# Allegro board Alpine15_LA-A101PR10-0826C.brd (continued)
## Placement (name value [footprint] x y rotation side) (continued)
Q11  PMST3904_SOT323-3~D  [PMST3904_SOT323-3]  142.6 74.84 90 top
Q12  MMST3904-7-F_SOT323-3~D  [MMST3904-7-F_SOT323-3]  171.58 135.2 270 top
Q13  PMST3904_SOT323-3~D  [PMST3904_SOT323-3]  62.03 67.6 270 top
Q14  PMST3904_SOT323-3~D  [PMST3904_SOT323-3]  172.9 113.86 180 top
Q15  PMST3904_SOT323-3~D  [PMST3904_SOT323-3]  156.9 53 90 bottom
Q16  PDTA114EU_SC70-3~D  [PDTA114EU_SC70-3]  226.79 32.33 270 top
Q19  DMN66D0LDW-7_SOT363-6~D  [DMN66D0LDW-7_SOT363-6]  223.08 105.15 90 bottom
Q20  -  [L2N7002WT1G_SC-70-3]  317.46 155.36 270 bottom
Q21  DMN66D0LDW-7_SOT363-6~D  [DMN66D0LDW-7_SOT363-6]  320.68 156.18 0 bottom
Q22  DMN66D0LDW-7_SOT363-6~D  [DMN66D0LDW-7_SOT363-6]  248.73 165.28 90 bottom
Q24  DMN66D0LDW-7_SOT363-6~D  [DMN66D0LDW-7_SOT363-6]  222.41 37.82 180 top
Q26  PDTA114EU_SC70-3~D  [PDTA114EU_SC70-3]  224.6 37.57 90 top
Q28  DMN66D0LDW-7_SOT363-6~D  [DMN66D0LDW-7_SOT363-6]  209.07 143.56 180 top
Q30  DMN66D0LDW-7_SOT363-6~D  [DMN66D0LDW-7_SOT363-6]  250.63 164.11 270 bottom
Q32  DMN66D0LDW-7_SOT363-6~D  [DMN66D0LDW-7_SOT363-6]  203.71 163.68 0 top
Q122  DMN66D0LDW-7_SOT363-6~D  [DMN66D0LDW-7_SOT363-6]  16.66 106.58 0 top
Q123  DMN66D0LDW-7_SOT363-6~D  [DMN66D0LDW-7_SOT363-6]  300.22 149.37 270 bottom
Q124  SI3457CDV-T1-GE3_TSOP6~D  [SI3457CDV-T1-GE3_TSOP6]  96.6 155.58 180 bottom
Q125  DMN66D0LDW-7_SOT363-6~D  [DMN66D0LDW-7_SOT363-6]  85.43 148.24 0 bottom
Q126  -  [LP2301ALT1G_SOT23-3]  86.86 158.7 0 bottom
Q133  BSS138W-7-F_SOT323-3~D  [BSS138W-7-F_SOT323-3]  161.43 166.09 180 top
Q135  BSS138W-7-F_SOT323-3~D  [BSS138W-7-F_SOT323-3]  167.59 166.53 270 top
Q137  -  [LP2301ALT1G_SOT23-3]  89.65 163.23 90 bottom
Q138  -  [LP2301ALT1G_SOT23-3]  84.85 137.36 90 bottom
Q140  DMN66D0LDW-7_SOT363-6~D  [DMN66D0LDW-7_SOT363-6]  95.92 162.54 180 bottom
Q142  -  [SI3456DDV-T1-GE3_TSOP6]  162.76 106.41 180 top
Q143  DMN66D0LDW-7_SOT363-6~D  [DMN66D0LDW-7_SOT363-6]  161.63 109.4 270 top
QC1  DMN66D0LDW-7_SOT363-6~D  [DMN66D0LDW-7_SOT363-6]  187.23 75.92 180 top
QC4  DMN66D0LDW-7_SOT363-6~D  [DMN66D0LDW-7_SOT363-6]  219.34 54.35 90 top
QC6  DMN66D0LDW-7_SOT363-6~D  [DMN66D0LDW-7_SOT363-6]  75.68 100.61 180 bottom
QC8  DMN66D0LDW-7_SOT363-6~D  [DMN66D0LDW-7_SOT363-6]  73.23 116.87 90 bottom
QC9  DMN66D0LDW-7_SOT363-6~D  [DMN66D0LDW-7_SOT363-6]  67.22 121.72 180 bottom
QC11  DMN66D0LDW-7_SOT363-6~D  [DMN66D0LDW-7_SOT363-6]  68.76 97.62 270 top
QD1  -  [BSS138-G_SOT23-3]  228.51 32.04 270 top
QV2806  DMN66D0LDW-7_SOT363-6~D  [DMN66D0LDW-7_SOT363-6]  26.95 119.65 0 bottom
QZ5  -  [DMN66D0LDW-7_SOT363-6]  29.05 118.16 270 top
QZ21  -  [DMN66D0LDW-7_SOT363-6]  59.2 87.28 270 top
QZ22  -  [DMN66D0LDW-7_SOT363-6]  17.8 111.29 270 bottom
R1  1K_0402_5%~D  [R_0402]  177.31 75.55 270 bottom
R2  1K_0402_5%~D  [R_0402]  172.5 70.02 180 bottom
R3  0_0402_5%~D  [R_0402]  203.22 64.6 90 bottom
R4  33_0402_5%~D  [R_0402]  204.11 64.6 90 bottom
R5  33_0402_5%~D  [R_0402]  208.55 65.52 270 bottom
R6  33_0402_5%~D  [R_0402]  204.99 64.6 90 bottom
R7  33_0402_5%~D  [R_0402]  207.66 65.52 270 bottom
R8  0_0402_5%~D  [R_0402]  191.66 132.19 270 top
R9  33_0402_5%~D  [R_0402]  205.88 65.52 270 bottom
R10  0_0402_5%~D  [R_0402]  203.72 73.62 90 bottom
R11  33_0402_5%~D  [R_0402]  207.28 73.62 90 bottom
R12  33_0402_5%~D  [R_0402]  206.39 73.62 90 bottom
R13  33_0402_5%~D  [R_0402]  205.5 73.62 90 bottom
R14  0_0402_5%~D  [R_0402]  199.2 71.67 0 bottom
R15  33_0402_5%~D  [R_0402]  199.66 62.95 90 bottom
R16  33_0402_5%~D  [R_0402]  198.39 63.87 270 bottom
R17  0_0402_5%~D  [R_0402]  202.84 73.62 90 bottom
R18  33_0402_5%~D  [R_0402]  204.61 73.62 90 bottom
R19  33_0402_5%~D  [R_0402]  201.44 62.95 90 bottom
R20  33_0402_5%~D  [R_0402]  196.61 63.87 270 bottom
R21  33_0402_5%~D  [R_0402]  195.6 63.87 270 bottom
R22  33_0402_5%~D  [R_0402]  201.95 73.62 90 bottom
R23  0_0402_5%~D  [R_0402]  200.55 63.87 270 bottom
R24  1K_0402_5%~D  [R_0402]  122.62 84.62 0 bottom
R25  100K_0402_5%~D  [R_0402]  193.69 153.74 180 top
R26  100K_0402_5%~D  [R_0402]  248.73 151.8 0 bottom
R27  100K_0402_5%~D  [R_0402]  13.97 31.21 90 bottom
R28  220K_0402_5%~D  [R_0402]  232.35 31.99 270 top
R29  66.5_0402_1%  [R_0402]  124.73 14.06 90 bottom
R30  66.5_0402_1%  [R_0402]  125.62 14.06 90 bottom
R31  66.5_0402_1%  [R_0402]  199.42 14.21 90 top
R32  2M_0402_5%~D  [R_0402]  233.24 31.99 270 top
R33  66.5_0402_1%  [R_0402]  200.57 14.21 90 top
R34  0_0402_5%~D  [R_0402]  230.64 25.92 180 top
R35  10K_0402_5%~D  [R_0402]  175.61 125.77 180 top
R36  100K_0402_5%~D  [R_0402]  200.34 132.16 270 top
R37  0_0402_5%~D  [R_0402]  185.29 93.79 270 top
R39  20K_0402_1%~D  [R_0402]  314.18 151.01 0 bottom
R40  2.7K_0402_5%~D  [R_0402]  171.67 158.91 180 top
R41  33_0402_5%~D  [R_0402]  201.06 73.62 90 bottom
R42  2.7K_0402_5%~D  [R_0402]  171.64 159.84 180 top
R43  33_0402_5%~D  [R_0402]  205.62 83.69 90 bottom
R44  1M_0402_5%~D  [R_0402]  182.48 169.54 90 top
R45  33_0402_5%~D  [R_0402]  197.5 62.95 90 bottom
R46  2.2K_0402_5%~D  [R_0402]  171.64 162.63 180 top
R47  1M_0402_5%~D  [R_0402]  183.37 169.54 90 top
R48  33_0402_5%~D  [R_0402]  204.67 83.69 90 bottom
R49  2.2K_0402_5%~D  [R_0402]  171.64 163.58 180 top
R50  0_0402_5%~D  [R_0402]  185.06 85.84 270 bottom
R51  0_0402_5%~D  [R_0402]  185.94 85.84 270 bottom
R52  0_0402_5%  [R0402_0OHM]  223.04 117.42 90 bottom
R53  1M_0402_1%  [R_0402]  32.4 54.44 90 bottom
R54  2.7K_0402_5%~D  [R_0402]  187.39 162.34 0 top
R55  2.2K_0402_5%~D  [R_0402]  173.75 151.5 270 top
R56  0_0402_5%~D  [R_0402]  186.83 85.84 270 bottom
R57  33_0402_5%~D  [R_0402]  206.77 64.6 90 bottom
R58  33_0402_5%~D  [R_0402]  203.65 83.69 90 bottom
R59  33_0402_5%~D  [R_0402]  202.76 83.69 90 bottom
R60  0_0402_5%~D  [R_0402]  187.72 85.84 270 bottom
R61  0_0402_5%~D  [R_0402]  224.65 135.01 180 top
R62  0_0402_5%~D  [R_0402]  224.65 134.12 180 top
R64  10K_0402_5%~D  [R_0402]  168.04 149.19 90 top
R65  2.2K_0402_5%~D  [R_0402]  159.4 151.09 90 top
R66  1M_0402_5%~D  [R_0402]  187.24 153.09 90 top
R67  0_0402_5%~D  [R_0402]  225.57 133.26 180 top
R68  0_0402_5%~D  [R_0402]  225.57 132.37 180 top
R69  1M_0402_5%~D  [R_0402]  174.64 151.5 270 top
R71  0_0402_5%~D  [R_0402]  80.92 36.74 0 bottom
R73  0_0402_5%~D  [R_0402]  213.25 122.03 180 top
R74  2.7K_0402_5%~D  [R_0402]  190.21 158.15 180 top
R75  0_0402_5%~D  [R_0402]  213.25 121.11 180 top
R76  0_0402_5%~D  [R_0402]  212.15 122.9 180 top
R77  0_0402_5%  [R0402_0OHM]  213.01 122.91 90 top
R91  1M_0402_5%~D  [R_0402]  171.67 160.82 180 top
R92  1M_0402_5%~D  [R_0402]  171.67 161.71 180 top
R93  0_0402_5%~D  [R_0402]  80.92 37.63 0 bottom
R94  0_0402_5%~D  [R_0402]  80.92 34.84 0 bottom
R95  0_0402_5%~D  [R_0402]  80.92 35.72 0 bottom
R96  0_0402_5%~D  [R_0402]  80.92 35.85 0 top
R97  0_0402_5%~D  [R_0402]  80.92 34.96 0 top
R98  0_0402_5%~D  [R_0402]  80.92 36.74 0 top
R99  0_0402_5%~D  [R_0402]  80.92 37.63 0 top
R100  0_0402_5%~D  [R_0402]  71.39 78.98 270 bottom
R101  0_0402_5%~D  [R_0402]  70.5 78.98 270 bottom
R102  0_0402_5%~D  [R_0402]  154.19 91.15 90 top
R104  0_0402_5%~D  [R_0402]  155.08 91.15 90 top
R105  0_0402_5%~D  [R_0402]  71.39 78.98 270 top
R106  0_0402_5%~D  [R_0402]  70.5 78.98 270 top
R107  0_0402_5%  [R0402_0OHM]  188.18 152.18 180 top
R108  100K_0402_5%~D  [R_0402]  164.48 108.29 90 top
R109  10K_0402_5%~D  [R_0402]  159.26 109.02 270 top
R110  0_0402_5%  [R0402_0OHM]  89.68 143.12 270 bottom
R120  1M_0402_5%~D  [R_0402]  166.88 184.76 270 top
R121  1M_0402_5%~D  [R_0402]  165.62 173.34 270 bottom
R122  10K_0402_5%~D  [R_0402]  217.77 127.52 270 top
R123  10K_0402_5%~D  [R_0402]  219.09 127.49 270 top
R124  10K_0402_5%~D  [R_0402]  224.13 118.34 270 bottom
R125  100K_0402_5%~D  [R_0402]  223.92 107.58 180 bottom
R126  100K_0402_5%~D  [R_0402]  224.14 104.02 0 bottom
R130  0_0805_5%  [R0805_0OHM]  277.51 171.91 180 bottom
R136  33_0402_5%~D  [R_0402]  309.24 159.6 270 bottom
R137  BLM15AG700SN1D_0402  [R_0402]  191.64 173.57 270 bottom
R139  BLM15AG700SN1D_0402  [R_0402]  188.09 173.57 270 bottom
R141  33_0402_5%~D  [R_0402]  190.75 173.57 270 bottom
R142  0_0402_5%~D  [R_0402]  300.34 147.01 0 bottom
R143  0_0402_5%  [R0402_0OHM]  188.98 173.57 270 bottom
R144  0_0402_5%  [R0402_0OHM]  189.87 173.57 270 bottom
R148  47_0402_5%~D  [R_0402]  307.34 158.68 90 bottom
R149  33_0402_5%~D  [R_0402]  308.23 158.68 90 bottom
R150  10K_0402_5%~D  [R_0402]  301.28 155.33 0 bottom
R152  39.2K_0402_1%~D  [R_0402]  313.71 158.58 90 bottom
R153  0_0402_5%  [R0402_0OHM]  299.35 156.73 180 bottom
R154  0_0402_5%  [R0402_0OHM]  269.86 184.03 0 bottom
R155  0_0402_5%  [R0402_0OHM]  87.95 80.94 0 bottom
R156  39.2K_0402_1%~D  [R_0402]  314.6 158.58 90 bottom
R157  20K_0402_1%~D  [R_0402]  315.48 158.58 90 bottom
R158  100K_0402_5%~D  [R_0402]  320.69 158.36 270 bottom
R159  100K_0402_5%~D  [R_0402]  319.68 158.36 270 bottom
R160  10K_0402_5%~D  [R_0402]  310.48 161.33 180 bottom
R161  100K_0402_5%~D  [R_0402]  159.4 166.86 270 top
R162  18_0402_5%  [R_0402]  314.47 149.64 0 top
R163  100K_0402_5%~D  [R_0402]  316.93 161.33 0 bottom
R164  100K_0402_5%~D  [R_0402]  168.93 166.48 270 top
R165  0_0402_5%  [R0402_0OHM]  90.77 80.94 180 bottom
R166  18_0402_5%  [R_0402]  314.47 148.75 0 top
R167  10K_0402_5%~D  [R_0402]  311.34 162.22 0 bottom
R168  10K_0402_5%~D  [R_0402]  107.13 115.35 0 top
R169  0_0402_5%  [R0402_0OHM]  192.64 145.42 0 top
R170  10K_0402_5%~D  [R_0402]  107.13 114.46 0 top
R171  10K_0402_5%~D  [R_0402]  197.42 155.53 270 top
R172  10K_0402_5%~D  [R_0402]  196.47 155.53 270 top
R175  0_0402_5%  [R0402_0OHM]  197.86 142.93 90 top
R176  4.7K_0402_5%~D  [R_0402]  194.7 143.52 180 top
R178  4.7K_0402_5%~D  [R_0402]  193.79 144.41 0 top
R179  0_0402_5%  [R0402_0OHM]  193.79 142.63 0 top
R180  0_0402_5%  [R0402_0OHM]  196.92 142.06 180 top
R181  0_0603_5%~D  [R0603_0OHM]  205.87 143.71 90 top
R183  0_0402_5%  [R0402_0OHM]  200.66 142.04 90 top
R184  1K_0402_5%~D  [R_0402]  199.77 154.62 90 top
R185  3.01K_0402_1%~D  [R_0402]  204.28 144.74 270 top
R187  2.2K_0402_5%  [R_0402]  310.2 147.09 270 bottom
R193  0_0402_5%  [R0402_0OHM]  188.1 135.67 90 top
R197  2.2K_0402_5%  [R_0402]  309.31 147.09 270 bottom
R201  0_0402_5%~D  [R_0402]  192.17 154.89 90 top
R205  191_0402_1%~D  [R_0402]  25.17 20.67 90 bottom
R206  1M_0402_5%~D  [R_0402]  200.65 143.84 0 top
R208  100K_0402_5%~D  [R_0402]  298.39 151.4 270 bottom
R211  4.7K_0402_1%~D  [R_0402]  20.45 31.85 90 bottom
R212  100K_0402_5%~D  [R_0402]  17.52 25.24 90 bottom
R214  100K_0402_5%~D  [R_0402]  16.64 26.16 270 bottom
R215  0_0402_5%~D  [R_0402]  311.42 177.36 0 bottom
R216  2.2K_0402_5%~D  [R_0402]  245.82 154.88 180 bottom
R217  2.2K_0402_5%~D  [R_0402]  245.82 157.55 180 bottom
R218  0_0402_5%~D  [R_0402]  244.91 155.77 0 bottom
R219  0_0402_5%~D  [R_0402]  244.91 156.66 0 bottom
R223  0_0402_5%  [R0402_0OHM]  326.91 176.24 90 bottom
R224  0_0402_5%~D  [R_0402]  320.39 181.77 180 top
R225  0_0402_5%~D  [R_0402]  327.8 176.24 90 bottom
R226  100K_0402_5%~D  [R_0402]  247.71 162.68 90 bottom
R227  100K_0402_5%~D  [R_0402]  247.71 165.09 90 bottom
R228  0_0402_5%~D  [R_0402]  313.88 177.38 270 bottom
R229  100K_0402_5%~D  [R_0402]  251.78 164.23 270 bottom
R230  10_0402_5%~D  [R_0402]  27.61 25.95 0 bottom
R231  0_0402_5%  [R0402_0OHM]  31.41 33.05 90 bottom
R232  2.7K_0402_5%~D  [R_0402]  171.67 158.03 180 top
R233  0_0402_5%  [R0402_0OHM]  314.77 177.38 270 bottom
R234  0_0402_5%  [R0402_0OHM]  308.17 177.12 270 bottom
R236  0_0402_5%  [R0402_0OHM]  307.28 177.12 270 bottom
R238  0_0402_5%  [R0402_0OHM]  304.61 177.12 270 bottom
R239  0_0402_5%  [R0402_0OHM]  305.5 177.12 270 bottom
R240  0_0402_5%  [R0402_0OHM]  306.39 177.12 270 bottom
R241  0_0402_5%  [R0402_0OHM]  309.82 186.85 0 top
R244  0_0402_5%  [R0402_0OHM]  314.21 187.36 180 top
R246  0_0402_5%~D  [R_0402]  21.11 77.19 180 bottom
R247  0_0402_5%~D  [R_0402]  21.11 78.21 180 bottom
R248  0_0402_5%~D  [R_0402]  20.76 79.12 180 bottom
R249  0_0402_5%~D  [R_0402]  21.95 80.29 180 top
R250  0_0402_5%~D  [R_0402]  20.76 80.26 180 bottom
R251  0_0402_5%~D  [R_0402]  21.95 81.31 180 top
R252  0_0402_5%  [R0402_0OHM]  167.64 172.46 90 bottom
R253  0_0402_5%  [R0402_0OHM]  168.65 172.46 90 bottom
R254  0_0402_5%  [R0402_0OHM]  170.15 173.38 270 top
R255  0_0402_5%  [R0402_0OHM]  169.61 172.46 90 bottom
R256  0_0402_5%  [R0402_0OHM]  171.11 173.38 270 top
R257  0_0402_5%  [R0402_0OHM]  170.62 172.46 90 bottom
R258  0_0402_5%  [R0402_0OHM]  174.05 173.38 270 top
R259  0_0402_5%  [R0402_0OHM]  166.72 172.46 90 bottom
R260  0_0402_5%  [R0402_0OHM]  168.22 173.38 270 top
R261  0_0402_5%  [R0402_0OHM]  169.14 173.38 270 top
R262  0_0402_5%  [R0402_0OHM]  172.12 173.38 270 top
R263  0_0402_5%  [R0402_0OHM]  171.54 172.46 90 bottom
R264  0_0402_5%  [R0402_0OHM]  173.04 173.38 270 top
R265  0_0402_5%  [R0402_0OHM]  172.55 172.46 90 bottom
R266  0_0402_5%  [R0402_0OHM]  173.47 172.46 90 bottom
R267  0_0402_5%  [R0402_0OHM]  174.94 173.38 270 top
R268  100K_0402_5%~D  [R_0402]  175.02 173.44 90 bottom
R269  0_0402_5%  [R0402_0OHM]  183.91 180.29 90 top
R270  0_0402_5%  [R0402_0OHM]  184.8 180.29 90 top
R271  100K_0402_5%~D  [R_0402]  176.67 184.16 0 top
R272  10K_0402_5%~D  [R_0402]  201.32 184.62 180 top
R273  33_0402_5%~D  [R_0402]  198.87 177.13 0 top
R274  0_0402_5%  [R0402_0OHM]  186.77 180.2 90 top
R275  0_0402_5%  [R0402_0OHM]  189 180.22 90 top
R276  0_0402_5%  [R0402_0OHM]  187.68 180.19 90 top
R277  0_0402_5%  [R0402_0OHM]  189.87 180.22 90 top
R282  100K_0402_5%~D  [R_0402]  182.69 118.78 0 top
R283  100K_0402_5%~D  [R_0402]  199.99 120.05 180 top
R284  100K_0402_5%~D  [R_0402]  194.82 132.16 270 top
R285  100K_0402_5%~D  [R_0402]  187.21 115.15 90 top
R286  100K_0402_5%~D  [R_0402]  199.99 121.83 180 top
R288  10K_0402_5%~D  [R_0402]  188.1 115.15 90 top
R289  100K_0402_5%~D  [R_0402]  196.72 132.16 270 top
R290  33_0402_5%~D  [R_0402]  181.04 134.32 270 top
R291  10K_0402_5%~D  [R_0402]  191.02 115.15 90 top
R292  100K_0402_5%~D  [R_0402]  199.99 120.94 180 top
R293  100K_0402_5%~D  [R_0402]  185.94 132.12 270 top
R294  0_0402_5%  [R0402_0OHM]  199.84 128.82 0 top
R295  100K_0402_5%~D  [R_0402]  190.14 115.15 90 top
R296  10K_0402_5%~D  [R_0402]  201.62 119.24 270 top
R297  0_0402_5%  [R0402_0OHM]  30.26 33.05 90 bottom
R298  100K_0402_5%~D  [R_0402]  190.62 132.18 270 top
R302  100K_0402_5%~D  [R_0402]  202.49 120.22 180 top
R303  100K_0402_5%~D  [R_0402]  192.72 132.29 270 top
R304  10K_0402_5%~D  [R_0402]  202.76 124.88 0 top
R305  100K_0402_5%~D  [R_0402]  185.06 132.12 270 top
R306  0_0402_5%  [R0402_0OHM]  29.25 33.05 90 bottom
R307  100K_0402_5%~D  [R_0402]  182.67 119.72 0 top
R308  100K_0402_5%~D  [R_0402]  200.75 127.93 180 top
R309  100K_0402_5%~D  [R_0402]  189.25 115.15 90 top
R310  10K_0402_5%~D  [R_0402]  194.96 115.15 90 top
R311  150_0402_1%~D  [R_0402]  186.07 158.66 0 top
R312  150_0402_1%~D  [R_0402]  186.07 160.06 0 top
R313  100K_0402_5%~D  [R_0402]  194.07 115.15 90 top
R315  0_0402_5%  [R0402_0OHM]  27.98 33.05 90 bottom
R316  0_0402_5%  [R0402_0OHM]  197.76 115.15 90 top
R317  100K_0402_5%~D  [R_0402]  199.84 126.15 0 top
R318  0_0402_5%  [R0402_0OHM]  189.74 132.18 270 top
R319  0_0402_5%  [R0402_0OHM]  182.68 130.37 0 top
R320  100K_0402_5%~D  [R_0402]  200.75 127.04 180 top
R321  1K_0402_5%~D  [R_0402]  183.59 129.42 180 top
R322  100K_0402_5%~D  [R_0402]  202.49 121.11 180 top
R323  0_0402_5%~D  [R_0402]  199.83 125.21 0 top
R324  33_0402_5%~D  [R_0402]  183.59 122.51 180 top
R325  10_0402_1%~D  [R_0402]  202.49 122 180 top
R326  1K_0402_5%~D  [R_0402]  193.61 131.38 90 top
R327  100K_0402_5%~D  [R_0402]  160.4 112.72 0 top
R328  100K_0402_5%~D  [R_0402]  158.44 116.22 270 top
R329  10K_0402_5%~D  [R_0402]  161.31 111.83 180 top
R330  10K_0402_5%~D  [R_0402]  160.21 116.22 270 top
R331  10K_0402_5%~D  [R_0402]  195.51 157.31 270 top
R332  0_0402_5%  [R0402_0OHM]  154.37 121.74 0 top
R333  0_0402_5%  [R0402_0OHM]  25.75 33.05 90 bottom
R334  0_0402_5%  [R0402_0OHM]  161.81 134.33 90 top
R335  10K_0402_5%~D  [R_0402]  160.04 135.24 270 top
R336  0_0402_5%  [R0402_0OHM]  175.61 123.99 180 top
R337  0_0402_5%  [R0402_0OHM]  27.02 33.05 90 bottom
R338  1K_0402_5%~D  [R_0402]  165.24 115.3 270 top
R339  0_0402_5%~D  [R_0402]  78.35 117.85 270 bottom
R340  10K_0402_5%~D  [R_0402]  170.07 132.7 270 top
R341  0_0402_5%  [R0402_0OHM]  27.61 23.86 0 bottom
R342  100K_0402_5%~D  [R_0402]  160.93 135.24 270 top
R343  100K_0402_5%~D  [R_0402]  165.12 132.7 270 top
R344  0_0402_5%~D  [R_0402]  76.57 118.35 0 bottom
R345  0_0402_5%~D  [R_0402]  76.57 117.44 0 bottom
R346  0_0402_5%~D  [R_0402]  77.65 99.1 90 bottom
R347  0_0402_5%~D  [R_0402]  76.75 100.01 270 bottom
R348  0_0402_5%~D  [R_0402]  79.24 117.85 270 bottom
R349  1K_0402_5%~D  [R_0402]  157.7 129.58 180 top
R350  0_0402_5%~D  [R_0402]  80.13 117.8 90 bottom
R351  150_0402_1%~D  [R_0402]  186.07 161.45 0 top
R352  1K_0402_5%~D  [R_0402]  164.92 112.54 270 top
R353  100K_0402_5%~D  [R_0402]  310.48 162.22 180 bottom
R354  10K_0402_5%~D  [R_0402]  200.75 123.99 180 top
R355  0_0402_5%~D  [R_0402]  78.35 118.72 0 bottom
R358  100K_0402_5%~D  [R_0402]  164.03 112.54 270 top
R360  100K_0402_5%~D  [R_0402]  140.39 137.57 90 top
R362  100K_0402_5%~D  [R_0402]  164.35 114.39 90 top
R363  100K_0402_5%~D  [R_0402]  169.18 132.7 270 top
R366  10K_0402_5%~D  [R_0402]  167.15 132.7 270 top
R367  1K_0402_5%~D  [R_0402]  157.83 119.29 180 top
R370  100K_0402_5%~D  [R_0402]  157.83 120.18 180 top
R371  100K_0402_5%~D  [R_0402]  175.61 126.78 180 top
R373  8.2K_0402_5%~D  [R_0402]  168.04 132.7 270 top
R374  0_0402_5%  [R0402_0OHM]  158.14 131.39 180 top
R375  43_0402_5%~D  [R_0402]  155.21 133.49 90 top
R376  10K_0402_5%~D  [R_0402]  175.48 117.51 180 top
R378  0_0402_5%  [R0402_0OHM]  157.3 114.93 90 top
R379  0_0402_5%  [R0402_0OHM]  156.78 125.77 0 top
R380  100K_0402_5%~D  [R_0402]  155.72 123.94 270 top
R381  4.7K_0402_5%~D  [R_0402]  157.7 124.88 180 top
R382  10_0402_1%~D  [R_0402]  174.69 128.69 0 top
R383  1K_0402_5%~D  [R_0402]  174.69 130.59 0 top
R384  100_0402_1%~D  [R_0402]  156.61 123.02 90 top
R386  1K_0402_5%~D  [R_0402]  167.59 110.99 90 top
R387  100K_0402_5%~D  [R_0402]  311.34 163.11 0 bottom
R388  49.9_0402_1%~D  [R_0402]  220.67 90.72 0 top
R389  100K_0402_5%~D  [R_0402]  72.03 95.16 180 top
R391  100K_0402_5%~D  [R_0402]  189.12 135.6 90 top
R392  33K_0402_5%  [R_0402]  166.26 114.39 90 top
R393  10K_0402_5%~D  [R_0402]  163.09 110.94 180 top
R394  1.58K_0402_1%  [R_0402]  174.56 116.62 0 top
R395  10K_0402_5%~D  [R_0402]  220.67 91.73 0 top
R396  10K_0402_5%~D  [R_0402]  221.76 100.04 90 top
R397  10K_0402_5%~D  [R_0402]  224.43 100.04 90 top
R398  100K_0402_5%~D  [R_0402]  220.67 92.62 0 top
R399  10K_0402_5%~D  [R_0402]  163.09 111.83 180 top
R400  0_0402_5%  [R0402_0OHM]  222.65 100.04 90 top
R402  8.2K_0402_5%~D  [R_0402]  173.5 132.7 270 top
R403  2.2K_0402_5%~D  [R_0402]  170.34 135.29 270 top
R404  4.7K_0402_5%~D  [R_0402]  149.42 103.96 270 top
R405  4.7K_0402_5%~D  [R_0402]  149.42 105.33 90 top
R406  0_0402_5%  [R0402_0OHM]  223.54 100.04 90 top
R407  0_0402_5%  [R0402_0OHM]  186.11 183.64 90 top
R408  10K_0402_5%~D  [R_0402]  175.61 124.88 180 top
R410  0_0402_5%  [R0402_0OHM]  27.61 24.75 0 bottom
R411  33_0402_5%~D  [R_0402]  168.67 141.06 90 top
R413  0_0402_5%  [R0402_0OHM]  163.45 138.61 90 top
R414  0_0402_5%~D  [R_0402]  164.4 138.61 90 top
R415  0_0402_5%  [R0402_0OHM]  185.22 183.64 90 top
R416  0_0402_5%  [R0402_0OHM]  167.59 108.71 270 top
R417  0_0402_5%~D  [R_0402]  165.82 108.71 270 top
R418  0_0402_5%  [R0402_0OHM]  166.7 108.71 270 top
R419  100K_0402_5%~D  [R_0402]  187.77 132.16 270 top
R421  0_0402_5%~D  [R_0402]  196.59 111.04 180 top
R422  0_0402_5%  [R0402_0OHM]  196.59 110.15 180 top
R423  0_0402_5%~D  [R_0402]  196.69 109.26 180 top
R424  0_0402_5%  [R0402_0OHM]  196.69 108.37 180 top
R425  0_0402_5%~D  [R_0402]  253.25 160.82 0 bottom
R426  0_0402_5%  [R0402_0OHM]  253.25 161.71 0 bottom
R428  10K_0402_5%~D  [R_0402]  223.54 38.31 90 top
R429  300_0402_5%  [R_0402]  226.28 35.85 180 top
R432  100K_0402_5%~D  [R_0402]  208.88 140.7 180 top
R433  300_0402_5%~D  [R_0402]  226.28 34.96 180 top
R435  300_0402_5%~D  [R_0402]  226.28 34.07 180 top
R436  300_0402_5%~D  [R_0402]  210.2 143.7 270 top
R438  300_0402_5%~D  [R_0402]  227.65 37.88 0 top
R440  10K_0402_5%~D  [R_0402]  167.83 139.25 90 top
R441  0_0402_5%  [R0402_0OHM]  148.53 103.96 270 top
R443  0_0402_5%  [R0402_0OHM]  18.29 33.4 270 bottom
R444  0_0402_5%  [R0402_0OHM]  148.53 105.33 90 top
R449  0_0402_5%~D  [R_0402]  147.58 105.33 90 top
R450  0_0402_5%~D  [R_0402]  147.58 103.96 270 top
R459  100K_0402_5%~D  [R_0402]  172.49 79.46 180 top
R460  10K_0402_5%~D  [R_0402]  14.88 109.51 90 bottom
R461  0_0402_5%  [R0402_0OHM]  153.09 117.67 0 top
R462  680_0402_1%  [R_0402]  18.18 106.72 270 bottom
R463  680_0402_1%  [R_0402]  18.18 107.61 90 bottom
R464  680_0402_1%  [R_0402]  17.16 103.42 270 bottom
R465  680_0402_1%  [R_0402]  17.16 98.08 270 bottom
R466  680_0402_1%  [R_0402]  17.16 104.3 90 bottom
R467  680_0402_1%  [R_0402]  18.05 100.75 270 bottom
R468  680_0402_1%  [R_0402]  17.16 99.1 90 bottom
R469  680_0402_1%  [R_0402]  18.05 101.64 90 bottom
R470  2.2K_0402_5%~D  [R_0402]  19.32 106.59 0 top
R471  2.2K_0402_5%~D  [R_0402]  15.59 108.5 180 top
R472  0_0402_5%~D  [R_0402]  15.59 109.38 180 top
R473  10K_0402_5%~D  [R_0402]  11.57 113.19 270 top
R474  20K_0402_5%~D  [R_0402]  14.88 111.42 90 bottom
R475  1M_0402_5%~D  [R_0402]  19.16 112.2 270 bottom
R476  10K_0402_5%~D  [R_0402]  341.39 159.85 90 top
R477  10K_0402_5%~D  [R_0402]  101.62 178.32 270 top
R478  10K_0402_5%~D  [R_0402]  225.93 39.23 180 top
R479  10K_0402_5%~D  [R_0402]  312.44 166.53 270 top
R480  10K_0402_5%~D  [R_0402]  245.3 161.96 0 bottom
R481  10K_0402_5%~D  [R_0402]  186.88 131.25 90 top
R482  0_0402_5%  [R0402_0OHM]  246.28 158.48 180 bottom
R483  0_0402_5%  [R0402_0OHM]  246.28 159.62 180 bottom
R484  100K_0402_5%~D  [R_0402]  188.74 132.19 270 top
R485  0_0402_5%~D  [R_0402]  109.34 116.57 0 top
R486  0_0402_5%  [R0402_0OHM]  93.76 13.95 90 top
R487  0_0402_5%  [R0402_0OHM]  94.75 13.95 90 top
R488  0_0402_5%~D  [R_0402]  109.4 112.91 0 top
R490  10K_0402_5%~D  [R_0402]  109.41 126.53 0 top
R491  2.2K_0402_5%~D  [R_0402]  156.46 135.27 270 top
R492  2.2K_0402_5%~D  [R_0402]  157.35 135.27 270 top
R556  4.7K_0402_5%~D  [R_0402]  188.31 167.3 180 top
R734  0_0402_5%  [R0402_0OHM]  76.67 27.09 180 bottom
R741  0_0402_5%  [R0402_0OHM]  195.49 87.46 0 top
R742  0_0402_5%  [R0402_0OHM]  195.49 88.47 0 top
R2576  100K_0402_5%~D  [R_0402]  92.6 157.85 270 bottom
R2577  100K_0402_5%~D  [R_0402]  168.93 94.22 270 top
R2578  47K_0402_5%~D  [R_0402]  91.71 156.93 90 bottom
R2579  0_0402_5%  [R0402_0OHM]  103.34 154.47 180 bottom
R2580  0_0402_5%  [R0402_0OHM]  103.34 155.49 180 bottom
R2581  100K_0402_5%~D  [R_0402]  138.75 110.68 90 top
R2582  2.2K_0402_5%~D  [R_0402]  112.53 122.56 180 top
R2583  12K_0402_1%  [R_0402]  125.19 119.54 180 top
R2584  2.2K_0402_5%~D  [R_0402]  112.53 123.45 180 top
R2585  10K_0402_5%~D  [R_0402]  128.67 122.85 180 top
R2586  100K_0402_5%~D  [R_0402]  112.51 120.95 180 top
R2588  0_0402_5%  [R0402_0OHM]  99.08 159.47 90 bottom
R2590  4.7K_0402_5%~D  [R_0402]  107.84 122.01 90 top
R2591  4.7K_0402_5%~D  [R_0402]  110.51 122.01 90 top
R2592  4.7K_0402_5%~D  [R_0402]  107.84 120.1 90 top
R2593  4.7K_0402_5%~D  [R_0402]  110.51 120.1 90 top
R2594  0_0402_5%  [R0402_0OHM]  100.09 159.47 90 bottom
R2595  0_0402_5%  [R0402_0OHM]  106.32 159.63 270 top
R2596  0_0402_5%  [R0402_0OHM]  106.32 156.3 90 top
R2597  0_0402_5%  [R0402_0OHM]  126.56 121.45 0 top
R2598  0_0402_5%  [R0402_0OHM]  126.56 120.56 0 top
R2599  0_0402_5%  [R0402_0OHM]  101.57 143.65 0 top
R2600  0_0402_5%  [R0402_0OHM]  101.59 142.79 0 top
R2601  0_0402_5%~D  [R_0402]  87.93 154.95 270 bottom
R2602  0_0402_5%  [R0402_0OHM]  87.04 154.95 270 bottom
R2605  47K_0402_5%~D  [R_0402]  93.49 165.09 270 bottom
R2626  2K_0402_5%  [R_0402]  300.75 161.28 270 top
R2627  4.7K_0402_5%~D  [R_0402]  294.15 162.85 0 top
R2628  4.7K_0402_5%~D  [R_0402]  298.09 160.36 90 top
R2629  4.7K_0402_5%~D  [R_0402]  299.86 160.36 90 top
R2630  4.7K_0402_5%~D  [R_0402]  298.97 160.36 90 top
R2631  4.7K_0402_5%~D  [R_0402]  301.77 160.36 90 top
R2633  4.7K_0402_5%~D  [R_0402]  300.16 170.19 270 top
R2634  4.7K_0402_5%~D  [R_0402]  297.37 170.19 270 top
R2635  4.7K_0402_5%~D  [R_0402]  299.21 170.19 270 top
R2636  4.7K_0402_5%~D  [R_0402]  298.26 170.19 270 top
R2637  4.7K_0402_5%~D  [R_0402]  296.48 170.19 270 top
R2644  4.99K_0402_1%~D  [R_0402]  302.78 161.28 270 top
R2646  0_0402_5%~D  [R_0402]  295.1 164.69 180 bottom
R2647  0_0402_5%~D  [R_0402]  295.1 163.74 180 bottom
R2648  0_0402_5%~D  [R_0402]  303.72 167.04 0 bottom
R2649  0_0402_5%~D  [R_0402]  303.72 166.15 0 bottom
R2650  0_0402_5%~D  [R_0402]  304.64 164.88 180 bottom
R2651  0_0402_5%~D  [R_0402]  304.64 163.99 180 bottom
R2652  0_0402_5%~D  [R_0402]  294.18 165.64 0 bottom
R2653  0_0402_5%~D  [R_0402]  294.18 166.59 0 bottom
R2654  0_0402_5%  [R0402_0OHM]  304.64 164.88 180 top
R2655  0_0402_5%  [R0402_0OHM]  304.64 163.99 180 top
R2656  0_0402_5%  [R0402_0OHM]  303.72 167.04 0 top
R2657  0_0402_5%  [R0402_0OHM]  303.72 166.15 0 top
R2658  0_0402_5%~D  [R_0402]  186.83 85.84 270 top
R2659  0_0402_5%~D  [R_0402]  187.72 85.84 270 top
R2660  0_0402_5%~D  [R_0402]  185.06 85.84 270 top
R2661  0_0402_5%~D  [R_0402]  185.94 85.84 270 top
R2662  0_0402_5%~D  [R_0402]  225.54 132.35 180 bottom
R2663  0_0402_5%~D  [R_0402]  225.54 133.23 180 bottom
R2664  0_0402_5%~D  [R_0402]  224.65 134.12 180 bottom
R2665  0_0402_5%~D  [R_0402]  224.65 135.01 180 bottom
R2678  100K_0402_5%~D  [R_0402]  97.37 140.37 180 bottom
R2688  0_0603_5%~D  [R0603_0OHM]  288.5 146.47 180 top
R2689  12K_0402_1%~D  [R_0402]  227.32 46.87 0 top
R2691  10K_0402_5%~D  [R_0402]  216.63 50.96 180 top
R2692  10K_0402_5%~D  [R_0402]  216.63 51.98 180 top
R2693  10K_0402_5%~D  [R_0402]  216.42 55.54 270 top
R2694  0_0402_5%  [R0402_0OHM]  217.79 45.27 0 top
R2695  100K_0402_5%~D  [R_0402]  218.13 50.96 0 top
R2696  100K_0402_5%~D  [R_0402]  218.08 53.07 270 top
R2697  0_0402_5%  [R0402_0OHM]  217.79 46.41 0 top
R2698  100K_0402_5%~D  [R_0402]  217.57 57.7 270 top
R2699  0_0402_5%  [R0402_0OHM]  216.63 49.06 180 top
R2700  10K_0402_5%~D  [R_0402]  218.99 49.06 180 top
R2701  10K_0402_5%~D  [R_0402]  218.99 48.17 180 top
R2702  0_0603_5%~D  [R0603_0OHM]  288.37 148.65 180 top
R2703  0_0603_5%~D  [R0603_0OHM]  288.37 150.91 180 top
R2704  0_0603_5%~D  [R0603_0OHM]  288.37 153.35 180 top
R2705  3.74K_0402_1%  [R_0402]  186.07 157.52 0 top
R3000  100_0402_1%~D  [R_0402]  147.01 109.51 0 top
RC1  330K_0402_1%~D  [R_0402]  165.71 55.66 0 top
RC2  330K_0402_1%~D  [R_0402]  186.33 54.22 270 top
RC3  1K_0402_1%~D  [R_0402]  171.09 53.94 90 top
RC4  0_0402_5%  [R0402_0OHM]  179.21 58.25 90 top
RC5  10M_0402_5%~D  [R_0402]  179.21 56.48 90 top
RC6  20K_0402_5%~D  [R_0402]  202.78 60.53 270 bottom
RC7  1M_0402_5%~D  [R_0402]  165.62 58.38 90 top
RC8  20K_0402_5%~D  [R_0402]  197.25 59.68 270 bottom
RC9  1K_0402_1%~D  [R_0402]  172.86 53.94 90 top
RC10  1K_0402_1%~D  [R_0402]  99.85 82.75 90 bottom
RC11  100K_0402_5%~D  [R_0402]  176.09 72.17 0 bottom
RC12  10K_0402_5%~D  [R_0402]  176.09 70.14 0 bottom
RC14  0_0402_5%  [R0402_0OHM]  165.6 93.28 180 top
RC16  0_0603_5%  [R0603_0OHM]  102.67 72.3 90 bottom
RC17  51_0402_1%~D  [R_0402]  102.77 83.66 270 bottom
RC18  51_0402_1%~D  [R_0402]  100.74 82.75 90 bottom
RC19  3.01K_0402_1%~D  [R_0402]  164.68 92.39 0 top
RC20  51_0402_1%~D  [R_0402]  101.53 72.73 90 bottom
RC22  51_0402_1%~D  [R_0402]  96.9 82.77 90 bottom
RC23  33_0402_5%~D  [R_0402]  171.97 53.94 90 top
RC24  33_0402_5%~D  [R_0402]  160.15 54.69 90 top
RC25  33_0402_5%~D  [R_0402]  163.47 58.38 90 top
RC26  33_0402_5%~D  [R_0402]  162.58 58.38 90 top
RC27  10K_0402_5%~D  [R_0402]  173.03 68.22 180 bottom
RC28  2.2K_0402_5%~D  [R_0402]  184.93 73.49 90 top
RC30  2.2K_0402_5%~D  [R_0402]  184.93 76.19 270 top
RC32  0_0402_5%~D  [R_0402]  115.33 118.99 270 top
RC33  0_0402_5%  [R0402_0OHM]  168.04 94.22 270 top
RC36  2.2K_0402_5%~D  [R_0402]  180.86 71.97 90 bottom
RC37  2.2K_0402_5%~D  [R_0402]  179.98 71.97 90 bottom
RC38  0_0402_5%  [R0402_0OHM]  203.88 58.44 180 top
RC40  0_0402_5%  [R0402_0OHM]  149.45 91.43 180 top
RC44  1M_0402_5%~D  [R_0402]  151.23 91.43 180 top
RC45  3.01K_0402_1%~D  [R_0402]  156.61 91.22 90 top
RC46  10K_0402_5%~D  [R_0402]  146.57 91.48 90 top
RC47  10K_0402_5%~D  [R_0402]  145.69 91.48 90 top
RC48  0_0402_5%  [R0402_0OHM]  142.53 94.72 90 top
RC49  0_0402_5%  [R0402_0OHM]  141.64 94.72 90 top
RC50  10K_0402_5%~D  [R_0402]  170.07 59.3 270 top
RC52  10K_0402_5%~D  [R_0402]  179.34 54.85 270 top
RC53  0_0402_5%  [R0402_0OHM]  141.62 92.32 270 top
RC54  0_0402_5%  [R0402_0OHM]  142.51 92.32 270 top
RC55  10K_0402_5%~D  [R_0402]  178.25 77.76 0 bottom
RC58  22_0402_5%~D  [R_0402]  213.03 54.14 0 top
RC59  0_0402_5%  [R0402_0OHM]  143.84 91.47 90 top
RC60  0_0402_5%  [R0402_0OHM]  144.8 91.47 90 top
RC61  22_0402_5%~D  [R_0402]  213.03 56.77 90 top
RC63  22_0402_5%~D  [R_0402]  203.86 57.57 270 top
RC64  22_0402_5%~D  [R_0402]  169.05 57.01 270 top
RC65  0_0402_5%  [R0402_0OHM]  170.45 57.01 270 top
RC66  22_0402_5%~D  [R_0402]  168.16 57.01 270 top
RC67  1.8K_0402_1%  [R_0402]  99.58 13.04 90 top
RC68  2_0402_1%  [R_0402]  101.4 13.96 270 top
RC69  1.8K_0402_1%  [R_0402]  100.47 13.96 270 top
RC70  10K_0402_5%~D  [R_0402]  186.38 60.74 0 top
RC72  0_0402_5%  [R0402_0OHM]  185.94 78.6 270 bottom
RC73  330K_0402_1%~D  [R_0402]  188.18 57.97 90 top
RC74  10K_0402_5%~D  [R_0402]  183.61 75.35 180 top
RC76  8.2K_0402_5%~D  [R_0402]  183.53 81.11 90 bottom
RC78  330K_0402_1%~D  [R_0402]  187.26 58.89 270 top
RC79  0_0402_5%~D  [R_0402]  164.35 59.3 270 top
RC80  8.2K_0402_5%~D  [R_0402]  178.25 78.65 0 bottom
RC81  8.2K_0402_5%~D  [R_0402]  184.42 82.03 270 bottom
RC82  0_0402_5%~D  [R_0402]  185.13 61.81 180 top
RC83  24.9_0402_1%~D  [R_0402]  103.9 13.96 270 top
RC84  0_0402_5%~D  [R_0402]  181.88 53.55 90 top
RC85  100_0402_1%~D  [R_0402]  177.45 96.73 90 top
RC86  0_0402_5%  [R0402_0OHM]  178.71 75.55 270 bottom
RC87  0_0402_5%  [R0402_0OHM]  186.33 58 90 top
RC88  0_0402_5%  [R0402_0OHM]  180.86 53.55 90 top
RC90  0_0402_5%  [R0402_0OHM]  189.63 73.52 270 top
RC91  0_0402_5%  [R0402_0OHM]  190.52 73.52 270 top
RC92  0_0402_5%  [R0402_0OHM]  188.74 73.52 270 top
RC93  0_0402_5%  [R0402_0OHM]  164.52 56.6 90 top
RC94  0_0402_5%  [R0402_0OHM]  187.29 61.76 180 top
RC95  0_0402_5%~D  [R_0402]  100.74 81.5 270 bottom
RC96  0_0402_5%~D  [R_0402]  101.88 83.66 270 bottom
RC97  0_0402_5%~D  [R_0402]  98.96 83.66 270 bottom
RC98  10K_0402_5%~D  [R_0402]  179.59 74.64 90 bottom
RC99  1K_0402_1%~D  [R_0402]  101.16 57.7 0 top
RC100  0_0402_5%  [R0402_0OHM]  203.01 54.9 0 top
RC101  0_0402_5%~D  [R_0402]  100.58 72.73 90 bottom
RC102  1K_0402_1%~D  [R_0402]  101.16 49.41 0 top
RC103  0_0402_5%~D  [R_0402]  102.52 81.5 270 bottom
RC104  0_0402_5%~D  [R_0402]  101.63 80.59 90 bottom
RC105  1K_0402_1%~D  [R_0402]  102.07 43.7 180 top
RC106  1K_0402_1%~D  [R_0402]  102.07 44.61 180 top
RC107  0_0402_5%  [R0402_0OHM]  102.06 45.7 180 top
RC108  0_0402_5%  [R0402_0OHM]  102.06 47.53 180 top
RC109  1K_0402_1%~D  [R_0402]  102.07 55.92 180 top
RC110  0_0402_5%  [R0402_0OHM]  102.07 50.3 180 top
RC111  0_0402_5%  [R0402_0OHM]  102.07 51.32 180 top
RC112  0_0402_5%  [R0402_0OHM]  102.07 52.21 180 top
RC113  49.9_0402_1%~D  [R_0402]  118.88 77.14 0 bottom
RC114  62_0402_5%~D  [R_0402]  115.56 76.14 180 top
RC115  10K_0402_5%~D  [R_0402]  119.21 73.98 270 top
RC116  1K_0402_1%~D  [R_0402]  186.58 82.21 90 top
RC117  56_0402_5%~D  [R_0402]  121.23 78.09 0 bottom
RC118  51_0402_1%~D  [R_0402]  121.23 82.28 0 bottom
RC119  51_0402_1%~D  [R_0402]  119.73 83.23 180 bottom
RC120  51_0402_1%~D  [R_0402]  121.23 77.07 0 bottom
RC121  0_0402_5%~D  [R_0402]  119.73 79.1 180 bottom
RC122  51_0402_1%~D  [R_0402]  118.81 81.2 0 bottom
RC123  0_0402_5%~D  [R_0402]  99.87 80.59 90 bottom
RC124  0_0402_5%~D  [R_0402]  97.79 83.69 270 bottom
RC125  200_0402_1%~D  [R_0402]  133.56 69.51 180 top
RC126  2_0402_1%  [R_0402]  157.4 25.84 180 top
RC127  51_0402_1%~D  [R_0402]  98.95 80.56 90 bottom
RC128  24.9_0402_1%~D  [R_0402]  155.6 24 0 top
RC129  121_0402_1%  [R_0402]  124.73 62.06 90 bottom
RC130  1.8K_0402_1%  [R_0402]  158.4 25 90 top
RC131  51_0402_1%~D  [R_0402]  98.67 72.73 90 bottom
RC132  1.8K_0402_1%  [R_0402]  157.46 24.95 180 top
RC133  100_0402_1%~D  [R_0402]  130.89 69.16 90 top
RC134  24.9_0402_1%~D  [R_0402]  154.32 81.19 0 top
RC135  0_0402_5%~D  [R_0402]  99.56 73.64 270 bottom
RC136  10K_0402_5%~D  [R_0402]  164.01 54.61 90 top
RC137  100K_0402_5%~D  [R_0402]  178.83 94.22 270 top
RC138  10K_0402_5%~D  [R_0402]  174.32 74.43 270 bottom
RC139  0_0402_5%~D  [R_0402]  175.23 93.38 180 top
RC140  10K_0402_5%~D  [R_0402]  175.66 97.65 270 top
RC141  0_0402_5%~D  [R_0402]  122.88 60.11 0 bottom
RC142  0_0402_5%  [R0402_0OHM]  102.07 53.1 180 top
RC143  0_0402_5%~D  [R_0402]  124.78 85.64 0 bottom
RC144  0_0402_5%~D  [R_0402]  189.18 59.68 0 top
RC145  0_0402_5%~D  [R_0402]  178.88 59.85 0 bottom
RC146  10K_0402_5%~D  [R_0402]  183.61 82.97 180 top
RC147  100K_0402_5%~D  [R_0402]  169.43 97.65 270 top
RC148  10K_0402_5%~D  [R_0402]  174.97 76.57 180 bottom
RC149  100K_0402_5%~D  [R_0402]  177.05 94.22 270 top
RC152  100K_0402_5%~D  [R_0402]  169.82 94.22 270 top
RC153  100K_0402_5%~D  [R_0402]  168.55 97.27 270 top
RC154  1K_0402_1%~D  [R_0402]  171.99 75.07 270 top
RC155  100K_0402_5%~D  [R_0402]  171.59 94.22 270 top
RC156  100K_0402_5%~D  [R_0402]  170.7 94.22 270 top
RC157  0_0402_5%~D  [R_0402]  58.94 79.74 270 top
RC158  100K_0402_5%~D  [R_0402]  172.48 93.31 90 top
RC159  22.6_0402_1%~D  [R_0402]  160.37 59.22 180 top
RC160  0_0402_5%~D  [R_0402]  92.81 14.38 90 bottom
RC161  3.01K_0402_1%~D  [R_0402]  152.67 97.32 270 top
RC162  0_0402_5%~D  [R_0402]  110.32 111.12 180 top
RC163  0_0402_5%  [R0402_0OHM]  147.59 92.37 270 top
RC164  0_0402_5%~D  [R_0402]  92.81 14.38 90 top
RC165  0_0402_5%~D  [R_0402]  58.94 79.74 270 bottom
RC166  10K_0402_5%~D  [R_0402]  179.72 94.22 270 top
RC168  49.9_0402_1%~D  [R_0402]  160.37 58.33 180 top
RC169  10K_0402_5%~D  [R_0402]  175.1 71.16 180 bottom
RC170  100K_0402_5%~D  [R_0402]  176.09 71.16 0 bottom
RC172  0_0402_5%  [R0402_0OHM]  124.78 84.62 0 bottom
RC173  2_0402_1%  [R_0402]  80.08 25.56 0 bottom
RC174  0_0402_5%  [R0402_0OHM]  183.61 83.98 180 top
RC175  10K_0402_5%~D  [R_0402]  180.79 62.01 0 bottom
RC176  0_0402_5%  [R0402_0OHM]  183.61 84.87 180 top
RC179  0_0402_5%~D  [R_0402]  59.83 79.74 270 top
RC180  0_0402_5%  [R0402_0OHM]  191.41 73.52 270 top
RC181  0_0402_5%  [R0402_0OHM]  181.7 62.9 180 bottom
RC182  22_0402_5%~D  [R_0402]  213.93 52.37 90 top
RC183  100K_0402_5%~D  [R_0402]  178.24 79.5 90 bottom
RC184  22_0402_5%~D  [R_0402]  213.91 56.77 90 top
RC185  100K_0402_5%~D  [R_0402]  173.45 79.67 180 bottom
RC186  499_0402_1%~D  [R_0402]  182.69 73.57 0 top
RC187  22_0402_5%~D  [R_0402]  202.96 57.57 270 top
RC188  0_0402_5%~D  [R_0402]  91.93 14.38 90 bottom
RC189  100K_0402_5%~D  [R_0402]  199.96 129.73 0 top
RC190  1K_0402_1%~D  [R_0402]  183.61 76.24 180 top
RC191  100K_0402_5%~D  [R_0402]  190.03 135.62 90 top
RC192  499_0402_1%~D  [R_0402]  182.69 74.46 0 top
RC193  10K_0402_5%~D  [R_0402]  171.21 97.65 270 top
RC194  0_0402_5%  [R0402_0OHM]  122.14 79.1 180 bottom
RC195  24.9_0402_1%~D  [R_0402]  79.09 24.55 180 bottom
RC196  0_0402_5%~D  [R_0402]  110.32 112.03 180 top
RC197  10K_0402_5%~D  [R_0402]  171.34 59.3 270 top
RC198  100K_0402_5%~D  [R_0402]  183.61 75.35 180 bottom
RC199  100K_0402_5%~D  [R_0402]  174.77 96.73 90 top
RC200  0_0402_5%~D  [R_0402]  91.93 14.38 90 top
RC201  0_0402_5%~D  [R_0402]  59.83 79.74 270 bottom
RC202  0_0402_5%~D  [R_0402]  213.06 53.29 270 top
RC204  0_0402_5%  [R0402_0OHM]  115.57 77.86 180 top
RC206  10K_0402_5%~D  [R_0402]  176.67 57.39 270 top
RC208  0_0402_5%  [R0402_0OHM]  122.14 81.2 180 bottom
RC209  0_0402_5%  [R0402_0OHM]  119.73 82.28 180 bottom
RC211  0_0402_5%  [R0402_0OHM]  175.48 114.72 180 top
RC217  1.8K_0402_1%  [R_0402]  78.17 26.58 0 bottom
RC218  10K_0402_5%~D  [R_0402]  172.1 97.65 270 top
RC221  1.8K_0402_1%  [R_0402]  79.09 25.56 180 bottom
RC222  1K_0402_1%~D  [R_0402]  173.43 74.43 270 bottom
RC230  10K_0402_5%~D  [R_0402]  180.48 74 90 bottom
RC232  1K_0402_1%~D  [R_0402]  122.08 71.87 180 bottom
RC233  1K_0402_1%~D  [R_0402]  119.73 72.94 180 bottom
RC235  49.9_0402_1%~D  [R_0402]  130.14 73.38 270 top
RC236  8.2K_0402_1%  [R_0402]  163.47 92.11 270 top
RC237  49.9_0402_1%~D  [R_0402]  161.04 54.69 90 top
RC238  1K_0402_1%~D  [R_0402]  132.02 73.2 180 top
RC239  1K_0402_1%~D  [R_0402]  122.08 72.94 180 bottom
RC240  1K_0402_1%~D  [R_0402]  122.08 74.02 180 bottom
RC241  1K_0402_1%~D  [R_0402]  119.73 74.02 180 bottom
RC242  0_0603_5%~D  [R_0603]  115.33 85.64 0 bottom
RC243  1K_0402_5%~D  [R_0402]  118.58 85.64 180 bottom
RC244  75_0402_1%~D  [R_0402]  117.4 76.03 270 bottom
RC245  0_0402_5%  [R0402_0OHM]  119.45 85.64 0 bottom
RC246  0_0402_5%  [R0402_0OHM]  116.48 82.16 270 bottom
RC247  0_0402_5%  [R0402_0OHM]  119.45 84.62 0 bottom
RC248  43_0402_5%~D  [R_0402]  125.31 76.87 180 bottom
RC249  110_0402_1%~D  [R_0402]  118.88 76.25 0 bottom
RC250  100_0402_1%~D  [R_0402]  124.78 82.97 0 bottom
RC253  150_0402_1%~D  [R_0402]  118.81 80.18 0 bottom
RC254  0_0805_5%  [R0805_0OHM]  163.21 100.24 270 top
RC255  10K_0402_5%~D  [R_0402]  117.49 83.27 90 bottom
RC256  10K_0402_5%~D  [R_0402]  116.48 84.19 270 bottom
RC258  10K_0402_5%~D  [R_0402]  121.23 80.18 0 bottom
RC259  10K_0402_5%~D  [R_0402]  115.46 83.27 90 bottom
RC260  100_0402_1%~D  [R_0402]  125.7 82.08 180 bottom
RC261  0_0402_5%  [R0402_0OHM]  191.15 54.22 270 top
RC262  0_0805_5%  [R0805_0OHM]  159.92 102.09 0 top
RC263  0_0402_5%  [R0402_0OHM]  183.45 56.26 270 top
RC264  0_0402_5%~D  [R_0402]  190.14 54.22 270 top
RC265  0_0402_5%~D  [R_0402]  193.13 66.84 180 top
RC267  0_0402_5%  [R0402_0OHM]  193.13 67.73 180 top
RC272  0_0402_5%~D  [R_0402]  171.57 71.56 90 top
RC275  5.11_0402_1%~D  [R_0402]  157.19 54.46 180 top
RC276  0_0603_5%~D  [R_0603]  170.32 102.02 0 top
RC279  0_0402_5%  [R0402_0OHM]  105.68 13.04 90 top
RC280  51_0402_1%~D  [R_0402]  85.66 51.6 0 top
RC282  10K_0402_5%~D  [R_0402]  173.88 97.65 270 top
RC283  1K_0402_1%~D  [R_0402]  175.23 94.4 180 top
RC284  10K_0402_5%~D  [R_0402]  170.32 97.65 270 top
RC285  20K_0402_5%~D  [R_0402]  176.17 94.22 270 top
RC286  10K_0402_5%~D  [R_0402]  212.15 123.79 180 top
RC287  1K_0402_1%~D  [R_0402]  172.99 98.51 90 top
RC288  1K_0402_1%~D  [R_0402]  173.37 93.31 90 top
RC289  10K_0402_5%~D  [R_0402]  177.94 94.22 270 top
RC290  10K_0402_5%~D  [R_0402]  178.32 97.65 270 top
RC291  10K_0402_5%~D  [R_0402]  172.99 97.65 270 top
RC297  1M_0402_5%~D  [R_0402]  223.52 45.66 0 top
RC305  10K_0402_5%~D  [R_0402]  176.55 97.65 270 top
RC306  10K_0402_5%~D  [R_0402]  177.4 76.57 180 bottom
RC315  10K_0402_5%~D  [R_0402]  102.16 127.8 270 bottom
RC324  10K_0402_5%~D  [R_0402]  103.08 126.88 90 bottom
RD1  0_0402_5%  [R0402_0OHM]  80.08 26.58 0 bottom
RD3  470_0402_5%~D  [R_0402]  106.57 13.04 90 top
RD5  0_0402_5%  [R0402_0OHM]  148.88 22.72 90 top
RD6  0_0402_5%  [R0402_0OHM]  149.89 22.72 90 top
RD7  0_0402_5%  [R0402_0OHM]  160.87 25.59 0 top
RD10  0_0402_5%  [R0402_0OHM]  225.44 28.69 270 top
RD11  0_0402_5%  [R0402_0OHM]  225.49 29.93 0 top
RD12  0_0402_5%  [R0402_0OHM]  129.56 14.31 90 bottom
RD13  0_0402_5%  [R0402_0OHM]  203.99 16.84 270 top
RE4  10_0402_1%~D  [R_0402]  189.5 176.14 90 top
RE5  10_0402_1%~D  [R_0402]  186.94 177.06 270 top
RP1  2.2K_0804_8P4R_5%  [RP_0804_8P4R]  166.75 100.18 270 top
RP2  10K_8P4R_5%  [RP_0804_8P4R]  154.26 125.91 180 top
RP3  10K_8P4R_5%  [RP_0804_8P4R]  182.83 72.06 0 bottom
RP4  4.7K_8P4R_5%  [RP_0804_8P4R]  168.15 135.99 270 top
RP5  100K_0804_8P4R_5%  [RP_0804_8P4R]  183.47 124.76 180 top
RP6  2.2K_0804_8P4R_5%  [RP_0804_8P4R]  184.69 169.18 90 top
RP7  2.2K_0804_8P4R_5%  [RP_0804_8P4R]  173.38 138.15 90 top
RP8  2.2K_0804_8P4R_5%  [RP_0804_8P4R]  183.73 85.62 180 bottom
RP9  10K_8P4R_5%  [RP_0804_8P4R]  176.23 79.15 180 bottom
RP10  10K_8P4R_5%  [RP_0804_8P4R]  184.23 80.31 180 top
RP11  10K_8P4R_5%  [RP_0804_8P4R]  184.23 77.39 180 top
RP12  10K_8P4R_5%  [RP_0804_8P4R]  186.13 78.89 0 top
RP13  10K_8P4R_5%  [RP_0804_8P4R]  183.72 60.22 0 top
RP14  10K_8P4R_5%  [RP_0804_8P4R]  193.76 64.03 180 bottom
RP15  2.2K_0804_8P4R_5%  [RP_0804_8P4R]  157.82 126.92 180 top
RP16  10K_8P4R_5%  [RP_0804_8P4R]  162.69 133.01 270 top
RP17  100K_0804_8P4R_5%  [RP_0804_8P4R]  163.07 115.8 270 top
RP18  100K_0804_8P4R_5%  [RP_0804_8P4R]  175.98 118.67 180 top
RTCD1  -  [BAT54CW_SOT323-3]  11.28 17.03 90 bottom
RTCR1  1K_0402_1%~D  [R_0402]  8.19 17.48 270 bottom
RV2  200_0402_1%~D  [R_0402]  53.23 86.4 0 bottom
RV29  10K_0402_5%~D  [R_0402]  97.65 77.71 270 bottom
RV34  100K_0402_5%~D  [R_0402]  66.48 106.12 0 top
RV35  100K_0402_5%~D  [R_0402]  71.53 116.92 90 bottom
RV45  2.2K_0402_5%~D  [R_0402]  60.72 115.1 270 bottom
RV46  2.2K_0402_5%~D  [R_0402]  61.61 115.1 270 bottom
RV48  100K_0402_5%~D  [R_0402]  67.7 113.92 90 bottom
RV49  2.2K_0402_5%~D  [R_0402]  68.3 122.65 270 bottom
RV50  2.2K_0402_5%~D  [R_0402]  68.35 124.86 180 bottom
RV88  10K_0402_5%  [R_0402]  68.84 84.46 90 bottom
RV89  10K_0402_1%~D  [R_0402]  57.92 115.09 270 bottom
RV90  10K_0402_1%~D  [R_0402]  56.84 115.09 270 bottom
RV92  10K_0402_1%~D  [R_0402]  55.64 115.05 270 bottom
RV93  10K_0402_1%~D  [R_0402]  75.27 114.38 180 bottom
RV94  10K_0402_1%~D  [R_0402]  74.36 115.33 0 bottom
RV2404  0_0402_5%  [R0402_0OHM]  65.79 105.04 0 top
RV2427  0_0402_5%  [R0402_0OHM]  68.01 91.33 0 top
RV2433  10K_0402_5%~D  [R_0402]  71.64 97.19 270 top
RV2435  10K_0402_5%~D  [R_0402]  68.01 90.44 0 top
RV2436  10K_0402_5%~D  [R_0402]  74.49 105.57 0 bottom
RV2437  10K_0402_1%~D  [R_0402]  33.16 85.18 270 bottom
RV2438  10K_0402_1%~D  [R_0402]  32.84 113.16 90 bottom
RV2439  10K_0402_1%~D  [R_0402]  32.2 85.18 270 bottom
RV2440  10K_0402_1%~D  [R_0402]  31.89 113.16 90 bottom
RV2441  10K_0402_5%~D  [R_0402]  58.87 115.09 270 bottom
RV2442  10K_0402_5%~D  [R_0402]  59.76 114.17 90 bottom
RV2444  10K_0402_5%~D  [R_0402]  62.11 110.33 270 top
RV2446  10K_0402_5%~D  [R_0402]  70.88 113.92 90 bottom
RV2447  10K_0402_5%~D  [R_0402]  25.35 101.6 90 bottom
RV2647  10K_0402_1%~D  [R_0402]  75.29 109.76 180 bottom
RV2648  10K_0402_1%~D  [R_0402]  74.37 108.87 0 bottom
RV2649  10K_0402_1%~D  [R_0402]  75.28 113.45 180 bottom
RV2650  10K_0402_1%~D  [R_0402]  74.36 112.56 0 bottom
RV2651  10K_0402_1%~D  [R_0402]  75.28 107.1 180 bottom
RV2652  10K_0402_1%~D  [R_0402]  74.36 107.99 0 bottom
RV2653  10K_0402_1%~D  [R_0402]  75.27 111.65 180 bottom
RV2654  10K_0402_1%~D  [R_0402]  74.36 110.69 0 bottom
RV2703  2.49K_0402_1%~D  [R_0402]  52.98 83.55 270 bottom
RV2704  60.4_0402_1%~D  [R_0402]  54 107.04 270 top
RV2705  60.4_0402_1%~D  [R_0402]  54.94 104.4 90 top
RV2706  162_0402_1%  [R_0402]  34.77 113.12 180 bottom
RV2707  80.6_0402_1%~D  [R_0402]  34.75 114.9 270 bottom
RV2708  80.6_0402_1%~D  [R_0402]  33.86 114.9 270 bottom
RV2709  1.33K_0402_1%~D  [R_0402]  32.03 115.93 270 top
RV2710  1.33K_0402_1%~D  [R_0402]  31.81 114.06 0 top
RV2711  1.33K_0402_1%~D  [R_0402]  33.6 115.85 270 top
RV2712  1.33K_0402_1%~D  [R_0402]  33.59 114.06 0 top
RV2713  1.33K_0402_1%~D  [R_0402]  32.09 83.45 180 top
RV2714  1.33K_0402_1%~D  [R_0402]  31.18 84.34 0 top
RV2715  1.33K_0402_1%~D  [R_0402]  31.52 97.61 180 top
RV2716  1.33K_0402_1%~D  [R_0402]  30.6 98.76 0 top
RV2717  162_0402_1%  [R_0402]  35.58 85.29 180 top
RV2718  80.6_0402_1%~D  [R_0402]  35.57 83.5 90 top
RV2719  80.6_0402_1%~D  [R_0402]  34.68 83.5 90 top
RV2720  40.2_0402_1%~D  [R_0402]  55.32 109.25 0 top
RV2721  42.2_0402_1%  [R_0402]  54.97 110.52 180 top
RV2722  51.1_0402_1%  [R_0402]  52.27 110.52 0 top
RV2723  40.2K_0402_1%~D  [R_0402]  67.18 107.52 0 top
RV2805  100K_0402_5%~D  [R_0402]  25.89 118.59 270 bottom
RV2906  243_0402_1%~D  [R_0402]  31 114.07 270 bottom
RV2907  243_0402_1%~D  [R_0402]  33.47 84.33 90 top
RV2908  243_0402_1%~D  [R_0402]  25.35 95.59 270 bottom
RV2909  243_0402_1%~D  [R_0402]  31.75 101.04 0 top
RZ10  22_0402_5%~D  [R_0402]  31.9 117.18 90 top
RZ11  22_0402_5%~D  [R_0402]  29.16 115.73 0 top
RZ40  22_0402_5%~D  [R_0402]  56.64 86.56 0 top
RZ41  22_0402_5%~D  [R_0402]  62.49 87.66 270 top
SW5  EVQPLHA15_4P  [SW_EVQPLHA15_4P]  227.03 122.57 180 top
SW6  EVQPLHA15_4P  [SW_EVQPLHA15_4P]  249.9 125.87 180 bottom
T92  PAD~D  [TPC12]  198.39 154.72 0 top
T93  PAD~D  [TPC12]  197.67 153.55 0 top
T171  PAD  [TPC12]  62.75 116.5 180 top
T186  PAD  [TPC12]  72.15 85.65 180 bottom
T187  PAD  [TPC12]  66.43 91.64 0 top
T188  PAD  [TPC12]  67.87 84.72 180 bottom
T189  PAD  [TPC12]  67.36 86.57 180 bottom
T190  PAD  [TPC12]  70.03 85.52 180 bottom
T191  PAD  [TPC12]  164.19 69.81 0 top
U1  -  [W25Q64FVSSIQ_SO8]  204.16 67.22 90 bottom
U2  -  [W25Q32FVSSIQ_SO8]  200.11 69.63 270 bottom
U4  -  [PI3USB102ZLEX_TQFN10_1P6X1P3]  150.06 108.55 0 top
U5  -  [74AUP1G07GW_TSSOP5]  229.17 27.24 0 top
U6  IDTVMM2320BKG8_BGA168  [IDTVMM2320BKG8_BGA_168P-NH]  175.64 154.94 90 top
U7  W25X10CLSNIG_SO8  [W25X10BVSNIG_SO8]  166.43 149.64 90 top
U11  PI3C3125LEX_TSSOP14~D  [PI3C3125LEX_TSSOP14]  159.47 157.95 0 top
U13  PI3C3125LEX_TSSOP14~D  [PI3C3125LEX_TSSOP14]  165.05 158.02 0 top
U15  LNG3DMTR_LGA16_3X3~D  [LNG3DMTR_LGA16_3X3]  217.58 123.01 90 top
U17  -  [ALC3226-CG_QFN48_7X7]  305.73 156.53 0 bottom
U18  TPS22966DPUR_SON14_2X3~D  [TPS22966DPUR_SON14_2X3]  269.69 181.94 0 bottom
U19  TPS22966DPUR_SON14_2X3~D  [TPS22966DPUR_SON14_2X3]  88.24 79.13 0 bottom
U20  TC7SH08FU_SSOP5~D  [TC7SH08FU_SSOP5]  194.45 156.79 180 top
U21  -  [WGI218LM-QQ89-B0_QFN48_6X6]  196.91 146.09 0 top
U22  -  [APE8988Y_SOT26-6]  215.66 185.2 270 top
U23  PI3L720ZHEX_TQFN42_9X3P5~D  [PI3L720ZHEX_TQFN42_9X3P5]  192.42 168.91 0 top
U24  TC7SH08FU_SSOP5~D  [TC7SH08FU_SSOP5]  201.79 154.76 0 top
U25  AT97SC3204-DX3A TSSOP 28P  [AT97SC3204-X2A14-AB_TSSOP28]  185.9 142.1 180 top
U27  OZ777FJ2LN_QFN48P_6X6  [OZ777FJ2LN_QFN48_6X6]  24.99 23.55 180 bottom
U28  SRV05-4.TCT_SOT23-6~D  [SRV05-4PTCT_SOT23-6]  255.74 185.05 180 top
U29  -  [APE8988Y_SOT26-6]  228.87 41.31 0 top
U30  TC7SH08FU_SSOP5~D  [TC7SH08FU_SSOP5]  245.7 150.52 90 bottom
U33  -  [APE8988Y_SOT26-6]  101.29 142.21 270 bottom
U34  -  [APE8988Y_SOT26-6]  218.08 119.54 270 top
U37  ECE5048-LZY_DQFN132_11X11~D  [ECE5048-LZY_DQFN132_11X11]  195.84 129.09 180 top
U38  MEC5075-LZY_DQFN132_11X11~D  [MEC5075-LZY_DQFN132_11X11]  162.44 118.19 0 top
U39  PI3V713-AZLEX_TQFN32_6X3~D  [PI3V713-AZLEX_TQFN32_6X3]  188.32 167.36 180 bottom
U41  RT9818A-44GU3_SC70-3~D  [RT9818A-44GU3_SC70-3]  165.91 141.39 270 top
U42  TC7SH08FU_SSOP5~D  [TC7SH08FU_SSOP5]  166.83 139.39 180 top
U43  TPS22966DPUR_SON14_2X3~D  [TPS22966DPUR_SON14_2X3]  167.74 105.53 180 top
U45  TPS22966DPUR_SON14_2X3~D  [TPS22966DPUR_SON14_2X3]  193.45 108.82 90 top
U46  TPS22966DPUR_SON14_2X3~D  [TPS22966DPUR_SON14_2X3]  255.67 160.06 90 bottom
U47  TC7SH08FU_SSOP5~D  [TC7SH08FU_SSOP5]  207.68 153.77 180 top
U51  TPS22966DPUR_SON14_2X3~D  [TPS22966DPUR_SON14_2X3]  262.54 151.76 180 bottom
U52  RTD2136R-CG_QFN48_6X6  [RTD2136S-VE-CG_QFN48_6X6]  116.16 120.98 0 top
U83  -  [PS8713BTQFN24GTR2_TQFN24_4X4]  298.15 163.03 0 top
U86  TC7SH08FU_SSOP5~D  [TC7SH08FU_SSOP5]  90.86 143.42 0 bottom
U87  TC7SH08FU_SSOP5~D  [TC7SH08FU_SSOP5]  145.22 111.05 90 top
U90  -  [USX2064-AEZG-TR_QFN36_6X6]  226.85 49.82 90 top
U91  PI2DBS6212ZHEX TQFN 28P  [PI2DBS212ZHEX_TQFN28_5P5X3P5]  185.6 95.34 0 top
U93  -  [PI5A3157CEX_SC70-6]  108.93 115.24 270 top
U94  -  [APE8939GN3_DFN8_3X3]  156.97 108.68 90 top
UC1  HASWELL-MCP-E-ULT_BGA1168  [HASWELL-MCP-E-ULT_BGA_1168P-T]  168.14 84.55 0 bottom
UC2  74AHC1G09GW_TSSOP5~D  [74AHC1G09GW_TSSOP5]  182.88 79.55 0 bottom
UC3  TC7SH08FU_SSOP5~D  [TC7SH08FU_SSOP5]  193.99 57.89 180 top
UC4  -  [74AUP1G07GW_TSSOP5]  184.85 56.89 270 top
UC5  -  [5V60034DCG8_SO8]  211.22 54.65 90 top
UC6  -  [74CBTLV3126BQ_DHVQFN14_2P5X3]  99.58 77.4 0 bottom
UC7  TC7SH08FU_SSOP5~D  [TC7SH08FU_SSOP5]  188.49 62.05 270 top
US1  -  [G547I2P81U_MSOP8]  24.2 71.18 180 bottom
UV1  N14M-GE-S-A2_FCBGA595~D  [N14M-GE-S-A2_FCBGA_595P]  70.93 110.54 180 bottom
UV4  MT41K256M16HA-107G-E_FBGA96~D  [MT41K256M16HA-125M-E_FBGA_96P]  39.92 103.9 90 bottom
UV5  MT41K256M16HA-107G-E_FBGA96~D  [MT41K256M16HA-125M-E_FBGA_96P]  39.92 110.3 270 top
UV6  MT41K256M16HA-107G-E_FBGA96~D  [MT41K256M16HA-125M-E_FBGA_96P]  39.93 88.15 90 bottom
UV7  MT41K256M16HA-107G-E_FBGA96~D  [MT41K256M16HA-125M-E_FBGA_96P]  39.93 94.55 270 top
UV14  TC7SH08FU_SSOP5~D  [TC7SH08FU_SSOP5]  96.57 80.82 0 bottom
Y1  27MHZ_12PF_X1E000021042600~D  [Y_X1E000021042600_4P]  190.14 153.59 90 top
Y3  25MHZ_18PF_7V25000034  [Y_7V25000034_4P]  202.92 142.27 270 top
Y4  32.768KHZ_12.5PF_Q13FC1350000~D  [Y_Q13FC1350000_2P]  155.67 117.23 270 top
Y6  24MHZ_12PF_X3G024000DC1H  [Y_X3G024000DC1H_4P]  221.92 42.59 0 top
YC1  32.768KHZ_12.5PF_Q13FC1350000~D  [Y_Q13FC1350000_2P]  181.76 59.04 270 top
YC2  24MHZ_12PF_X3G024000DC1H  [Y_X3G024000DC1H_4P]  151.18 95.93 180 top
YV2401  27MHZ_12PF_X3G027000FC1H-H~D  [Y_X3G025000DI1H-H_4P]  63.81 112.58 0 top

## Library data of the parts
